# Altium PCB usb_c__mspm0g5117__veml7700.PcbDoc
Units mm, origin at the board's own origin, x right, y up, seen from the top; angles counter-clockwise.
Board outline 92 x 60 mm, 2 copper layers (Top, Bottom), stack 0 mm thick; 31 components, 27 nets, 168 pads, 52 vias.
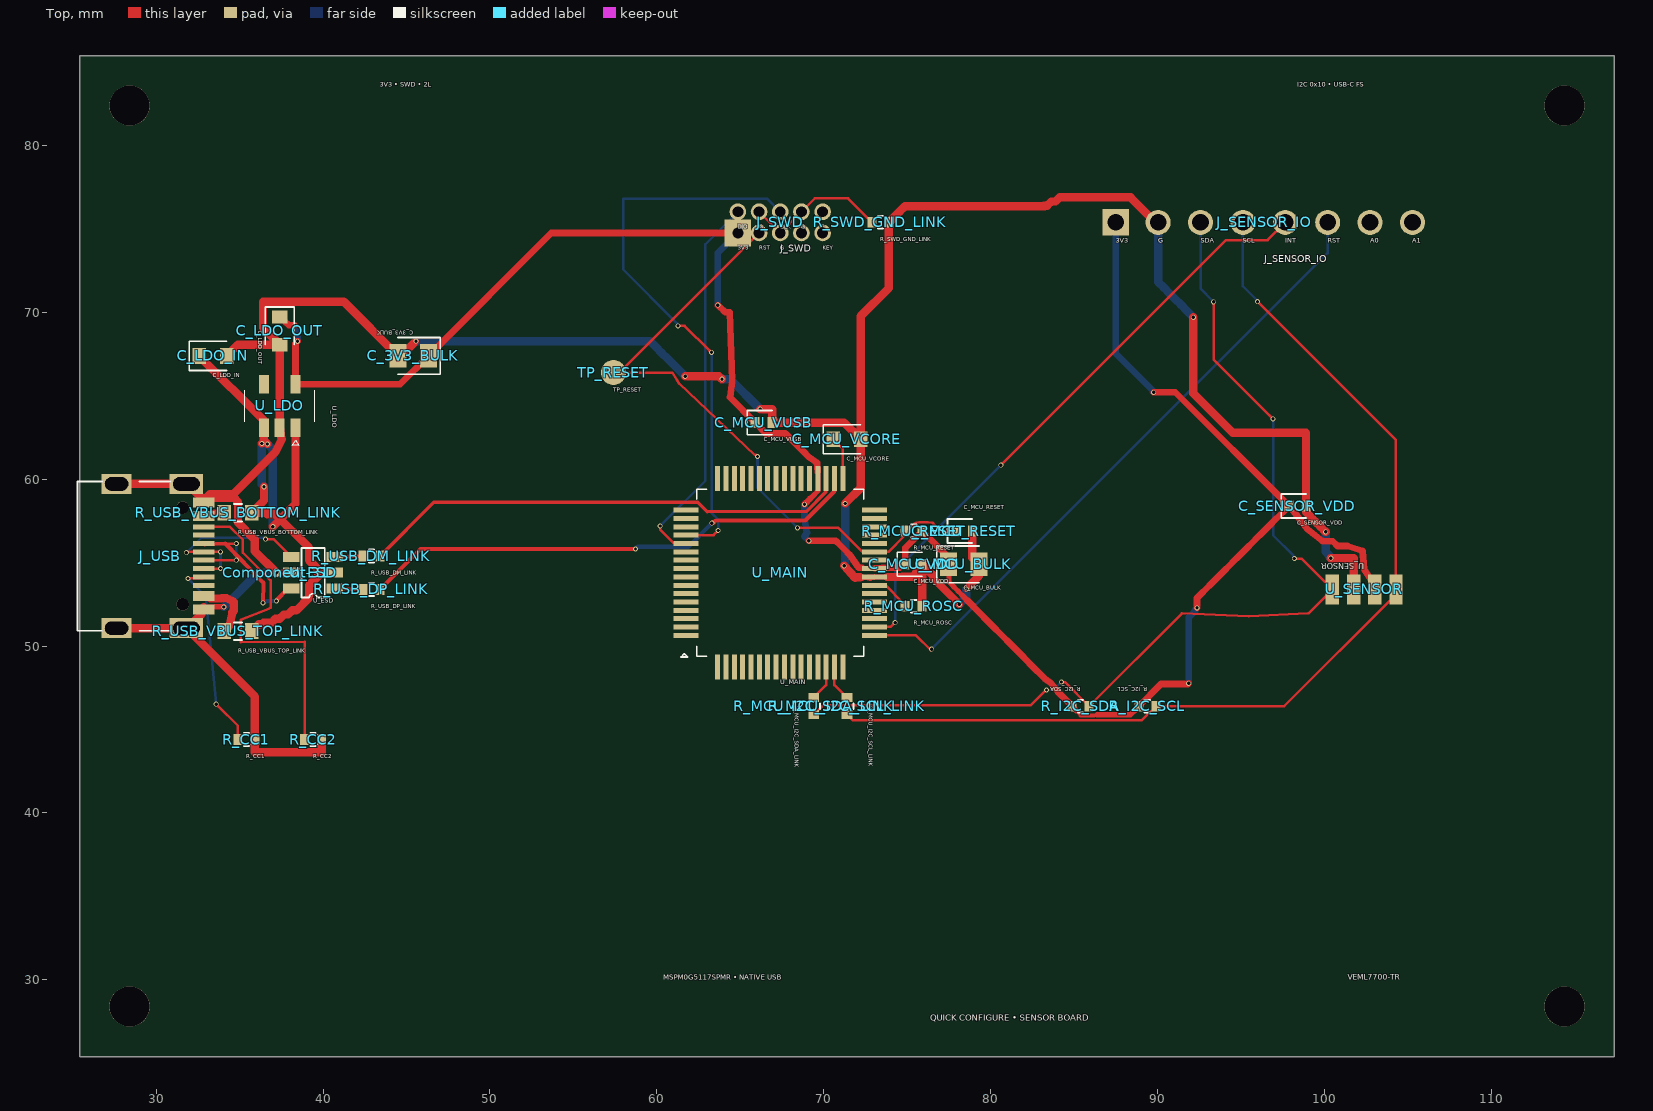
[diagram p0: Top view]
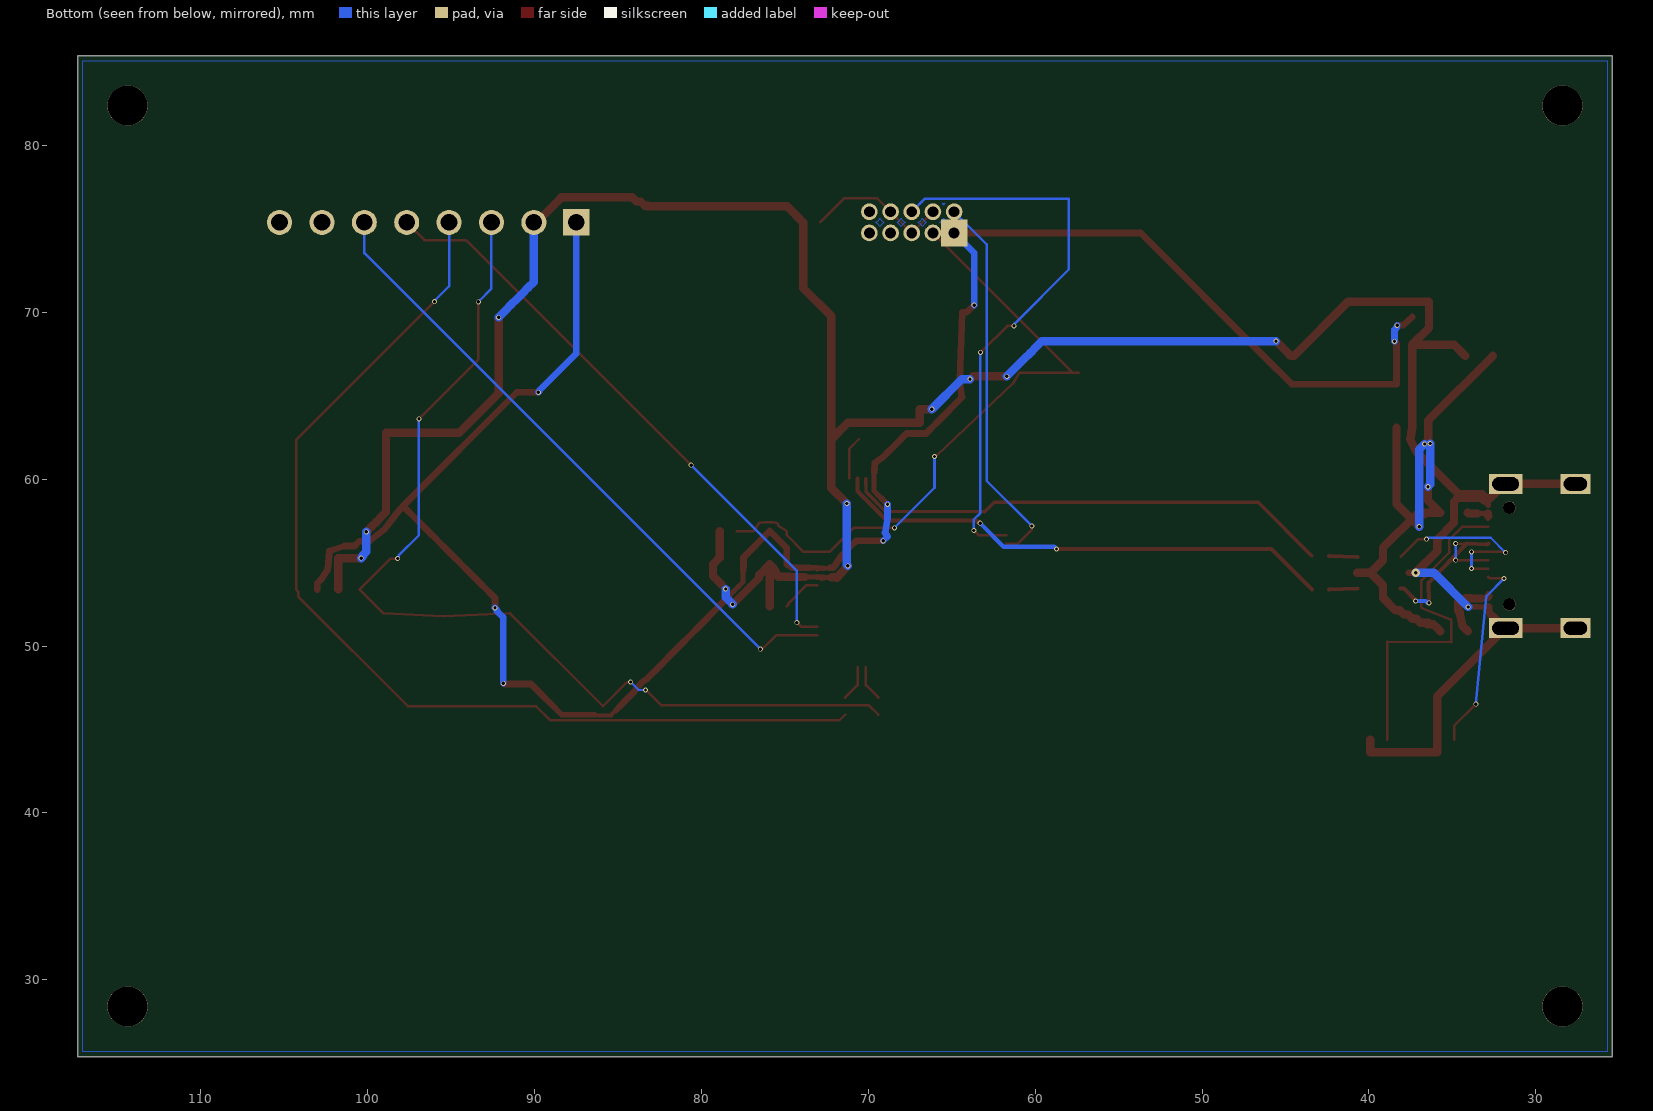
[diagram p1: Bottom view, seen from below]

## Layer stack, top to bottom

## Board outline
25.4,85.4 117.4,85.4 117.4,25.4 25.4,25.4

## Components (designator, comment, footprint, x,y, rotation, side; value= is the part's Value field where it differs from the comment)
C_3V3_BULK "" TSCIRCUIT-2.8500x1.4000mm 45.4,67.4 r180 top
C_LDO_IN "" TSCIRCUIT-2.4500x0.9500mm 33.4,67.4 r0 top
C_LDO_OUT "" TSCIRCUIT-0.9500x2.4500mm 37.4,68.9 r270 top
C_MCU_BULK "" TSCIRCUIT-2.8500x1.4000mm 78.4,54.9 r0 top
C_MCU_RESET "" TSCIRCUIT-1.5600x0.6400mm 78.4,56.9 r0 top
C_MCU_VCORE "" TSCIRCUIT-2.4500x0.9500mm 71.4,62.4 r0 top
C_MCU_VDD "" TSCIRCUIT-1.5600x0.6400mm 75.4,54.9 r0 top
C_MCU_VUSB "" TSCIRCUIT-1.5600x0.6400mm 66.4,63.4 r0 top
C_SENSOR_VDD "" TSCIRCUIT-1.5600x0.6400mm 98.4,58.4 r0 top
Component-31 "" TSCIRCUIT-0.5000x0.5000mm 37.2,54.4 r0 top
J_SENSOR_IO "" TSCIRCUIT-19.2800x1.5000mm 96.4,75.4 r0 top
J_SWD "" TSCIRCUIT-6.0800x2.2700mm 67.4,75.4 r0 top
J_USB "" TSCIRCUIT-6.7732x9.8502mm 30.113,55.4 r90 top
R_CC1 "" TSCIRCUIT-1.5600x0.6400mm 35.4,44.4 r0 top
R_CC2 "" TSCIRCUIT-1.5600x0.6400mm 39.4,44.4 r0 top
R_I2C_SCL "" TSCIRCUIT-1.5600x0.6400mm 89.4,46.4 r180 top
R_I2C_SDA "" TSCIRCUIT-1.5600x0.6400mm 85.4,46.4 r180 top
R_MCU_I2C_SCL_LINK "" TSCIRCUIT-0.6400x1.5600mm 71.4,46.4 r270 top
R_MCU_I2C_SDA_LINK "" TSCIRCUIT-0.6400x1.5600mm 69.4,46.4 r270 top
R_MCU_RESET "" TSCIRCUIT-1.5600x0.6400mm 75.4,56.9 r0 top
R_MCU_ROSC "" TSCIRCUIT-1.5600x0.6400mm 75.4,52.4 r0 top
R_SWD_GND_LINK "" TSCIRCUIT-1.5600x0.6400mm 73.4,75.4 r0 top
R_USB_DM_LINK "" TSCIRCUIT-1.5600x0.6400mm 42.9,55.4 r0 top
R_USB_DP_LINK "" TSCIRCUIT-1.5600x0.6400mm 42.9,53.4 r0 top
R_USB_VBUS_BOTTOM_LINK "" TSCIRCUIT-2.4500x0.9500mm 34.9,58 r0 top
R_USB_VBUS_TOP_LINK "" TSCIRCUIT-2.4500x0.9500mm 34.9,50.9 r0 top
TP_RESET "" TSCIRCUIT-1.5000x1.5000mm 57.4,66.4 r0 top
U_ESD "" TSCIRCUIT-3.6000x2.5000mm 39.4,54.4 r0 top
U_LDO "" TSCIRCUIT-2.5000x3.7000mm 37.4,64.4 r270 top
U_MAIN "" TSCIRCUIT-12.8000x12.8000mm 67.4,54.4 r0 top
U_SENSOR "" TSCIRCUIT-4.6100x1.8000mm 102.4,53.4 r0 top

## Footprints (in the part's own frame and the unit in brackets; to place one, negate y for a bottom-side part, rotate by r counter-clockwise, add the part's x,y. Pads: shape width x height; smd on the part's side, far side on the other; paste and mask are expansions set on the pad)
TSCIRCUIT-0.5000x0.5000mm [mm]
TSCIRCUIT-0.6400x1.5600mm [mm]
  rect 0.54x0.64 smd: 1(-0.51,0) 2(0.51,0)
  silkscreen extent -0.15,-0.38 0.15,0.38
TSCIRCUIT-0.9500x2.4500mm [mm]
  rect 0.8x0.95 smd: 1(-0.825,0) 2(0.825,0)
  silkscreen extent -1.43,-0.87 0.82,0.88
TSCIRCUIT-1.5000x1.5000mm [mm]
  round 1.5 smd: 1(0,0)
TSCIRCUIT-1.5600x0.6400mm [mm]
  rect 0.54x0.64 smd: 1(-0.51,0) 2(0.51,0)
  silkscreen extent -0.98,-0.72 0.51,0.72
TSCIRCUIT-2.4500x0.9500mm [mm]
  rect 0.8x0.95 smd: 1(-0.825,0) 2(0.825,0)
  silkscreen extent -1.42,-0.87 0.82,0.87
TSCIRCUIT-2.5000x3.7000mm [mm]
  rect 1.1x0.6 smd: 1(1.3,0.95) 2(1.3,0) 3(1.3,-0.95) 4(-1.3,-0.95) 5(-1.3,0.95)
  silkscreen extent -0.95,-2.1 2.35,2.1
TSCIRCUIT-2.8500x1.4000mm [mm]
  rect 1.025x1.4 smd: 1(-0.913,0) 2(0.913,0)
  silkscreen extent -1.63,-1.1 0.91,1.1
TSCIRCUIT-3.6000x2.5000mm [mm]
  rect 1x0.6 smd: 1(-1.3,-0.95) 2(-1.3,0) 3(-1.3,0.95) 4(1.3,0.95) 5(1.3,0) 6(1.3,-0.95)
  silkscreen extent -0.7,-1.49 0.7,1.49
TSCIRCUIT-4.6100x1.8000mm [mm]
  rect 0.8x1.8 smd: 1(1.905,0) 2(0.635,0) 3(-0.635,0) 4(-1.905,0)
TSCIRCUIT-6.0800x2.2700mm [mm]
  rect 1.6x1.6 hole 0.65: 1(-2.54,-0.635)
  round 1 hole 0.65: 2(-2.54,0.635) 3(-1.27,0.635) 4(0,0.635) 5(1.27,0.635) 6(2.54,0.635) 7(2.54,-0.635) 8(1.27,-0.635) 9(0,-0.635) 10(-1.27,-0.635)
TSCIRCUIT-6.7732x9.8502mm [mm]
  rect 0.3x1.3 smd: 1(-3.35,-2.737) 2(-3.05,-2.737) 3(-2.55,-2.737) 4(-2.25,-2.737) 5(-1.75,-2.737) 6(-1.25,-2.737) 7(-0.75,-2.737) 8(-0.25,-2.737) 9(0.25,-2.737) 10(0.75,-2.737) 11(1.25,-2.737) 12(1.75,-2.737) 13(2.55,-2.737) 14(2.25,-2.737) 15(3.35,-2.737) 16(3.05,-2.737)
  rect 1.2x2 hole 0.8 slot 1.6 at 90 deg: 17(-4.325,-1.693) 18(4.325,-1.693)
  rect 1.2x1.8 hole 0.8 slot 1.4 at 90 deg: 19(4.325,2.487) 20(-4.325,2.487)
  round 0.75 hole 0.75 unplated: NPTH-1(-2.9,-1.468) NPTH-2(2.9,-1.468)
  silkscreen extent -4.47,-0.75 4.47,4.83
TSCIRCUIT-12.8000x12.8000mm [mm]
  rect 1.5x0.3 smd: 1(-5.65,-3.75) 2(-5.65,-3.25) 3(-5.65,-2.75) 4(-5.65,-2.25) 5(-5.65,-1.75) 6(-5.65,-1.25) 7(-5.65,-0.75) 8(-5.65,-0.25) 9(-5.65,0.25) 10(-5.65,0.75) 11(-5.65,1.25) 12(-5.65,1.75) 13(-5.65,2.25) 14(-5.65,2.75) 15(-5.65,3.25) 16(-5.65,3.75) 33(5.65,3.75) 34(5.65,3.25) 35(5.65,2.75) 36(5.65,2.25) 37(5.65,1.75) 38(5.65,1.25) 39(5.65,0.75) 40(5.65,0.25) 41(5.65,-0.25) 42(5.65,-0.75) 43(5.65,-1.25) 44(5.65,-1.75) 45(5.65,-2.25) 46(5.65,-2.75) 47(5.65,-3.25) 48(5.65,-3.75)
  rect 0.3x1.5 smd: 17(-3.75,5.65) 18(-3.25,5.65) 19(-2.75,5.65) 20(-2.25,5.65) 21(-1.75,5.65) 22(-1.25,5.65) 23(-0.75,5.65) 24(-0.25,5.65) 25(0.25,5.65) 26(0.75,5.65) 27(1.25,5.65) 28(1.75,5.65) 29(2.25,5.65) 30(2.75,5.65) 31(3.25,5.65) 32(3.75,5.65) 49(3.75,-5.65) 50(3.25,-5.65) 51(2.75,-5.65) 52(2.25,-5.65) 53(1.75,-5.65) 54(1.25,-5.65) 55(0.75,-5.65) 56(0.25,-5.65) 57(-0.25,-5.65) 58(-0.75,-5.65) 59(-1.25,-5.65) 60(-1.75,-5.65) 61(-2.25,-5.65) 62(-2.75,-5.65) 63(-3.25,-5.65) 64(-3.75,-5.65)
  silkscreen extent -5.95,-5.05 5,5
TSCIRCUIT-19.2800x1.5000mm [mm]
  rect 1.6x1.6 hole 1: 1(-8.89,0)
  round 1.5 hole 1: 2(-6.35,0) 3(-3.81,0) 4(-1.27,0) 5(1.27,0) 6(3.81,0) 7(6.35,0) 8(8.89,0)

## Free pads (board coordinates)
  round 2.4 hole 2.4 unplated: NPTH-3(28.4,28.4) NPTH-4(114.4,28.4) NPTH-5(28.4,82.4) NPTH-6(114.4,82.4)

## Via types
v1: diameter 0.3, hole 0.2, Top to Bottom, 51 vias
v2: diameter 0.5, hole 0.2, Top to Bottom, 1 vias

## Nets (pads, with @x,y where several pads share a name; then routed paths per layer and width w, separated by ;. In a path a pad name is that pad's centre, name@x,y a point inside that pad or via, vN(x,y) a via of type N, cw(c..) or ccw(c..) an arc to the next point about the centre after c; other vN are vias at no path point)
".J_SWD > .pin2 to .U_MAIN > .pin12": J_SWD.2 U_MAIN.12 | length 22.9
  Top w0.15: v1(60.2,57.2) 60.2,56.987 61.037,56.15 U_MAIN.12
  Bottom w0.15: v1(60.2,57.2) 62.903,59.903 62.903,74.078 J_SWD.2
".J_SWD > .pin4 to .U_MAIN > .pin13": J_SWD.4 U_MAIN.13 | length 34.3
  Top w0.15: v1(61.273,69.197) 61.668,69.197 63.155,67.709 63.177,67.709 v1(63.28,67.606) ; U_MAIN.13 63.4,56.65 v1(63.683,56.933)
  Bottom w0.15: v1(61.273,69.197) 61.219,69.251 61.219,69.348 57.975,72.592 57.975,76.819 66.616,76.819 J_SWD.4 ; v1(63.28,67.606) 63.28,57.987 63.691,57.576 63.691,57.077 63.691,56.941 v1(63.683,56.933)
".U_MAIN > .pin42 to .R_MCU_ROSC > .pin1": R_MCU_ROSC.1 U_MAIN.42 | length 2.4
  Top w0.15: U_MAIN.42 73.713,53.658 74.762,52.598 74.76,52.53 R_MCU_ROSC.1
GND: C_3V3_BULK.2 C_LDO_IN.2 C_LDO_OUT.2 C_MCU_BULK.2 C_MCU_RESET.2 C_MCU_VCORE.2 C_MCU_VDD.2 C_MCU_VUSB.2 C_SENSOR_VDD.2 J_SENSOR_IO.2 J_USB.1 J_USB.2 J_USB.15 J_USB.16 J_USB.17 J_USB.18 J_USB.19 J_USB.20 R_CC1.2 R_CC2.2 R_MCU_ROSC.2 R_SWD_GND_LINK.2 U_ESD.2 U_LDO.2 U_MAIN.41 U_SENSOR.3 | length 183.4
  Top w0.275: J_USB.2 J_USB.2@33.25,52.35
  Top w0.3: J_USB.1@32.699,51.9 J_USB.1 J_USB.1@32.849,52.2 ; J_USB.15@32.699,58.9 J_USB.15 ; J_USB.16 32.999,58.6 33.04,58.641 33.141,58.641 33.4,58.9 33.499,58.9 ; J_USB.16@32.849,58.6 J_USB.15 ; J_USB.15@32.999,58.9 J_USB.15 ; J_USB.2@33.25,52.35 33.499,52.35 ; 72.3,54.12 72.425,54.12 72.55,54.12 U_MAIN.41@72.675,54.117 ; U_MAIN.41 73.144,54.15 73.237,54.15 73.331,54.15 73.425,54.15 73.519,54.15 73.612,54.15 73.706,54.15 U_MAIN.41@73.8,54.15
  Top w0.325: J_USB.16 J_USB.16@32.849,58.6 ; 33.499,52.35 33.651,52.35 v1(34.053,52.35)
  Top w0.337: U_MAIN.41@72.675,54.117 U_MAIN.41@72.796,54.106
  Top w0.35: v1(78.551,53.425) v1@78.567,53.441
  Top w0.375: 45.429,68.145 45.435,68.145 v1(45.568,68.278) ; U_MAIN.41@72.796,54.106 U_MAIN.41
  Top w0.4: 37.2,54.4 U_ESD.2@37.6,54.4 ; 72.175,54.12 72.3,54.12 ; v1@78.567,53.441 v1@78.567,53.459
  Top w0.425: v1@78.567,53.459 78.815,53.708
  Top w0.437: 76.536,54.102 v1(78.132,52.506)
  Top w0.45: 76.536,54.102 76.536,54.256
  Top w0.475: U_MAIN.41@73.8,54.15 74.253,54.15 74.707,54.15
  Top w0.5: J_USB.20 J_USB.17 ; J_USB.19 J_USB.18 31.874,59.725 32.474,59.125 32.699,58.9 ; 32.699,51.9 32.474,51.675 31.874,51.075 J_USB.17 ; J_USB.1@32.849,52.2 J_USB.2 ; 32.999,58.9 33.199,59.1 34.6,59.1 37.15,61.65 37.512,62.398 37.456,62.749 U_LDO.2 C_LDO_OUT.2 ; 33.499,58.9 34.65,58.9 34.9,58.65 34.9,57.4 35.9,56.4 35.9,55.7 37.2,54.4 ; C_LDO_IN.2 34.9,68.075 C_LDO_OUT.2 ; R_CC2.2 39.91,43.65 35.91,43.65 R_CC1.2 35.91,46.971 J_USB.17 ; 45.429,68.145 45.181,67.897 44.932,67.648 44.684,67.4 C_3V3_BULK.2 41.237,70.65 36.4,70.65 36.4,69.075 C_LDO_OUT.2 ; v1(61.702,66.175) 62.107,66.175 62.513,66.175 62.918,66.175 63.324,66.175 63.729,66.175 63.885,66.019 63.908,66.019 v1(63.912,66) ; v1(66.2,64.2) 66.91,64.2 C_MCU_VUSB.2 71.225,63.4 C_MCU_VCORE.2 ; v1(71.23,54.813) 71.902,54.081 72.05,54.12 72.175,54.12 ; v1(71.292,58.547) 72.225,59.48 C_MCU_VCORE.2 ; 74.707,54.15 75.4,54.15 75.66,54.65 C_MCU_VDD.2 ; R_MCU_ROSC.2 C_MCU_VDD.2 ; 76.536,54.256 76.536,54.274 C_MCU_VDD.2 ; 78.815,53.708 79.064,53.956 79.313,54.205 79.313,54.552 C_MCU_BULK.2 78.91,55.303 C_MCU_RESET.2 ; J_SENSOR_IO.2 89.9,75.4 88.4,76.9 84.15,76.9 83.9,76.65 83.65,76.65 83.4,76.4 83.202,76.4 83.235,76.366 82.748,76.366 82.261,76.366 81.773,76.366 81.286,76.366 80.799,76.366 80.311,76.366 79.824,76.366 79.337,76.366 78.849,76.366 78.362,76.366 77.875,76.366 77.387,76.366 76.9,76.366 76.413,76.366 75.925,76.366 75.438,76.366 74.951,76.366 74.876,76.366 74.554,76.044 74.232,75.722 R_SWD_GND_LINK.2 73.91,71.464 72.225,69.779 72.225,69.287 72.225,68.795 72.225,68.303 72.225,67.812 72.225,67.32 72.225,66.828 72.225,66.336 72.225,65.844 72.225,65.352 72.225,64.86 72.225,64.368 72.225,63.876 72.225,63.384 72.225,62.892 C_MCU_VCORE.2 ; v1(92.163,69.711) 92.163,69.255 92.163,68.798 92.163,68.342 92.163,67.885 92.163,67.429 92.163,66.973 92.163,66.516 92.163,66.06 92.163,65.603 92.163,65.147 92.5,64.81 92.838,64.472 93.175,64.135 93.512,63.798 93.85,63.46 94.187,63.123 94.524,62.786 98.91,62.786 C_SENSOR_VDD.2 98.91,58.03 99.198,57.742 99.486,57.454 99.774,57.166 100.062,56.878 v1(100.086,56.854) ; v1(100.398,55.276) 101.765,55.276 U_SENSOR.3
  Bottom w0.5: v1(34.053,52.35) 36.103,54.4 37.2,54.4 ; v1(45.568,68.278) 46.052,68.278 46.536,68.278 47.019,68.278 47.503,68.278 47.987,68.278 48.471,68.278 48.955,68.278 49.439,68.278 49.922,68.278 50.406,68.278 50.89,68.278 51.374,68.278 51.858,68.278 52.342,68.278 52.825,68.278 53.309,68.278 53.793,68.278 54.277,68.278 54.761,68.278 55.245,68.278 55.728,68.278 56.212,68.278 56.696,68.278 57.18,68.278 57.664,68.278 58.148,68.278 58.631,68.278 59.115,68.278 59.599,68.278 59.947,67.93 60.295,67.582 60.642,67.235 60.99,66.887 61.338,66.539 61.686,66.191 v1(61.702,66.175) ; v1(63.912,66) 64.4,66 v1(66.2,64.2) ; v1(71.23,54.813) 71.292,54.875 v1(71.292,58.547) ; v1(78.132,52.506) 78.193,52.567 78.193,52.574 78.372,52.753 78.551,52.933 v1(78.551,53.425) ; J_SENSOR_IO.2 90.05,74.953 90.05,74.506 90.05,74.059 90.05,73.612 90.05,73.165 90.05,72.718 90.05,72.271 90.05,71.824 90.389,71.485 90.728,71.146 91.067,70.807 91.406,70.468 91.745,70.129 92.084,69.79 v1(92.163,69.711) ; v1(100.086,56.854) 100.086,56.457 100.086,56.061 100.086,55.664 100.305,55.446 100.305,55.369 v1(100.398,55.276)
MAIN_RESET: C_MCU_RESET.1 J_SWD.10 R_MCU_RESET.1 TP_RESET.1 U_MAIN.38 | length 39.4
  Top w0.15: v1(66.036,61.371) 65.94,61.467 65.87,61.467 61.348,65.731 60.937,66.4 TP_RESET.1 57.765,66.4 J_SWD.10 ; v1(68.435,57.088) 70.889,57.088 72.31,55.667 73.033,55.667 U_MAIN.38 73.889,55.65 74.889,56.651 R_MCU_RESET.1@74.889,56.899 ; R_MCU_RESET.1 75.4,57.22 75.434,57.351 75.542,57.405 75.741,57.423 76.047,57.425 76.251,57.425 76.537,57.386 76.892,56.9 C_MCU_RESET.1
  Bottom w0.15: v1(66.036,61.371) 66.036,59.492 68.418,57.11 68.418,57.105 v1(68.435,57.088)
MCU_I2C_SCL_LOCAL: R_MCU_I2C_SCL_LINK.1 U_MAIN.50 | length 2.2
  Top w0.15: U_MAIN.50 70.65,47.66 R_MCU_I2C_SCL_LINK.1
MCU_I2C_SDA_LOCAL: R_MCU_I2C_SDA_LINK.1 U_MAIN.51 | length 2.2
  Top w0.15: R_MCU_I2C_SDA_LINK.1 70.15,47.66 U_MAIN.51
MSPM0_VCORE: C_MCU_VCORE.1 U_MAIN.32 | length 2.6
  Top w0.15: C_MCU_VCORE.1 71.15,61.825 U_MAIN.32
SENSOR_ADDR0: J_SENSOR_IO.7
SENSOR_ADDR1: J_SENSOR_IO.8
SENSOR_INT: J_SENSOR_IO.5 U_MAIN.47 | length 36.5
  Top w0.15: U_MAIN.47 74,51.15 74.212,51.362 74.238,51.362 v1(74.287,51.411) ; v1(80.625,60.847) 94.118,74.34 96.61,74.34 J_SENSOR_IO.5
  Bottom w0.15: v1(74.287,51.411) 74.287,54.509 80.58,60.802 v1(80.625,60.847)
SENSOR_RESET: J_SENSOR_IO.6 U_MAIN.48 | length 39.2
  Top w0.15: U_MAIN.48 75.532,50.65 76.428,49.753 76.428,49.776 v1(76.472,49.82)
  Bottom w0.15: v1(76.472,49.82) 100.21,73.558 J_SENSOR_IO.6
SENSOR_SCL: J_SENSOR_IO.4 R_I2C_SCL.1 R_MCU_I2C_SCL_LINK.2 U_SENSOR.1 | length 62.3
  Top w0.15: R_MCU_I2C_SCL_LINK.2 71.743,45.547 89.014,45.547 89.057,45.547 R_I2C_SCL.1 97.597,46.4 104.162,52.957 104.158,53.253 U_SENSOR.1 104.305,62.354 v1(96.008,70.651)
  Bottom w0.15: J_SENSOR_IO.4 95.13,71.573 95.959,70.744 95.959,70.7 v1(96.008,70.651)
SENSOR_SDA: J_SENSOR_IO.3 R_I2C_SDA.1 R_MCU_I2C_SDA_LINK.2 U_SENSOR.4 | length 60.9
  Top w0.15: R_MCU_I2C_SDA_LINK.2 69.971,46.448 82.163,46.459 82.42,46.461 83.299,47.34 83.331,47.34 v1(83.362,47.371) ; v1(84.249,47.851) 84.459,47.851 R_I2C_SDA.1 91.47,51.958 95.475,51.8 99.055,51.96 U_SENSOR.4 98.646,55.249 v1(98.213,55.249) ; v1(93.377,70.642) 93.377,67.185 96.765,63.797 v1(96.937,63.625)
  Bottom w0.15: v1(83.362,47.371) 83.786,47.388 84.204,47.806 v1(84.249,47.851) ; J_SENSOR_IO.3 92.59,71.429 93.317,70.702 v1(93.377,70.642) ; v1(96.937,63.625) 96.937,56.647 98.161,55.423 98.161,55.301 v1(98.213,55.249)
swd-ground-1-to-2: J_SWD.3 J_SWD.5 J_SWD.9 R_SWD_GND_LINK.1 | length 8.8
  Top w0.15: J_SWD.3 J_SWD.9 J_SWD.5 69.481,76.846 71.471,76.846 71.471,76.819 R_SWD_GND_LINK.1
usb-dm-device: R_USB_DM_LINK.1 U_ESD.4 | length 1.7
  Top w0.25: U_ESD.4 R_USB_DM_LINK.1
usb-dm-mcu: R_USB_DM_LINK.2 U_MAIN.30 | length 29.6
  Top w0.2: R_USB_DM_LINK.2 46.638,58.628 62.455,58.628 63.023,58.061 68.962,58.069 70.142,59.249 U_MAIN.30
usb-dm-port-tie: J_USB.7 J_USB.9 U_ESD.3 | length 11.2
  Top w0.15: v1(31.8,55.6) 31.87,55.6 31.92,55.65 J_USB.9 v1(33.85,55.65) ; J_USB.7 v1(33.85,54.65) ; v1(36.552,56.413) 37.037,56.413 U_ESD.3
  Bottom w0.15: v1(31.8,55.6) 32.697,56.497 36.165,56.497 36.457,56.497 36.546,56.407 v1(36.552,56.413) ; v1(33.85,54.65) v1(33.85,55.65)
usb-dp-device: R_USB_DP_LINK.1 U_ESD.6 | length 1.7
  Top w0.25: U_ESD.6 R_USB_DP_LINK.1
usb-dp-mcu: R_USB_DP_LINK.2 U_MAIN.31 | length 30.5
  Top w0.25: R_USB_DP_LINK.2 45.837,55.827 v1(58.728,55.827) ; v1(63.302,57.373) 63.358,57.429 63.43,57.429 63.531,57.53 68.895,57.522 70.658,59.285 U_MAIN.31
  Bottom w0.25: v1(58.728,55.827) 58.861,55.96 58.89,55.96 61.889,55.96 v1(63.302,57.373)
usb-dp-port-tie: J_USB.8 J_USB.10 U_ESD.1 | length 12.8
  Top w0.15: J_USB.8 v1(34.8,55.15) ; J_USB.10 v1(34.8,56.15)
  Top w0.25: J_USB.10 32.909,56.09 34.135,56.153 36.435,53.797 v1(36.4,52.6) ; v1@37.201,52.711 37.201,52.75 37.901,53.45 U_ESD.1
  Bottom w0.15: v1(34.8,55.15) v1(34.8,56.15)
  Bottom w0.25: v1(36.4,52.6) 36.404,52.604 36.496,52.604 36.603,52.711 v1(37.201,52.711)
USB_CC1: J_USB.6 R_CC1.1 | length 11.7
  Top w0.15: v1(31.901,54.055) 32.754,54.055 J_USB.6 ; v1(33.586,46.524) 33.699,46.411 33.709,46.411 34.89,45.23 R_CC1.1
  Bottom w0.15: v1(31.901,54.055) 31.894,54.048 32.952,52.991 v1(33.586,46.524)
USB_CC2: J_USB.12 R_CC2.1 | length 20.4
  Top w0.15: J_USB.12 34.418,57.15 35.182,56.386 35.182,55.613 36.855,53.94 36.855,52.307 36.75,52.25 35.063,51.575 35.063,50.225 38.89,50.271 R_CC2.1
USB_VBUS_BOTTOM_LOCAL: J_USB.13 J_USB.14 R_USB_VBUS_BOTTOM_LINK.1 | length 1.5
  Top w0.3: J_USB.14 J_USB.14@32.849,57.8 ; J_USB.13 32.927,57.95 33.005,57.95 33.083,57.95 33.161,57.95 33.239,57.95 33.317,57.95 33.394,57.95 33.472,57.95 33.499,57.95
  Top w0.475: J_USB.13@32.849,57.8 J_USB.13 ; 33.499,57.95 R_USB_VBUS_BOTTOM_LINK.1@33.762,57.95
  Top w0.5: R_USB_VBUS_BOTTOM_LINK.1@33.762,57.95 34.025,57.95 R_USB_VBUS_BOTTOM_LINK.1
USB_VBUS_TOP_LOCAL: J_USB.3 J_USB.4 R_USB_VBUS_TOP_LINK.1 | length 4.1
  Top w0.275: J_USB.3 J_USB.3@33.247,52.85
  Top w0.3: J_USB.3 32.849,53 J_USB.4
  Top w0.475: J_USB.3@33.247,52.85 33.644,52.85 33.928,52.867
  Top w0.5: 33.928,52.867 33.945,52.884 34.212,52.884 34.65,52.65 34.65,52.123 34.562,52.035 34.475,51.623 34.387,51.211 R_USB_VBUS_TOP_LINK.1
VBUS5: C_LDO_IN.1 R_USB_VBUS_BOTTOM_LINK.2 R_USB_VBUS_TOP_LINK.2 U_ESD.5 U_LDO.1 U_LDO.3 | length 38.2
  Top w0.5: C_LDO_IN.1 36.45,63.525 U_LDO.3 ; R_USB_VBUS_TOP_LINK.2 35.93,51.106 36.136,51.311 36.521,51.311 36.431,51.4 36.9,51.4 37.15,51.65 37.4,51.65 37.65,51.9 37.9,51.9 38.15,52.15 38.4,52.15 39.15,52.9 39.15,53.65 39.9,54.4 ; v1(36.325,62.15) 36.45,62.275 U_LDO.3 ; v1(36.459,59.554) 36.459,59.144 36.459,58.734 36.214,58.489 35.97,58.245 R_USB_VBUS_BOTTOM_LINK.2 36.225,58 36.725,58 36.65,57.925 36.65,57.9 37.15,57.9 39.15,55.9 39.15,55.15 39.9,54.4 ; v1(36.656,62.118) 36.45,62.325 U_LDO.3 ; v1(36.985,57.166) 38.35,58.531 U_LDO.1 ; 39.9,54.4 U_ESD.5 39.9,54.4
  Bottom w0.5: v1(36.325,62.15) 36.325,59.688 v1(36.459,59.554) ; v1(36.656,62.118) 36.985,61.79 v1(36.985,57.166)
VCC_3V3: C_3V3_BULK.1 C_LDO_OUT.1 C_MCU_BULK.1 C_MCU_VDD.1 C_MCU_VUSB.1 C_SENSOR_VDD.1 J_SENSOR_IO.1 J_SWD.1 R_I2C_SCL.2 R_I2C_SDA.2 R_MCU_RESET.2 U_LDO.5 U_MAIN.29 U_MAIN.40 U_SENSOR.2 | length 133.6
  Top w0.25: R_I2C_SDA.2@85.143,46.147 85.396,45.894 85.4,45.85 85.667,45.85 85.933,45.85 86.2,45.85 86.395,45.89
  Top w0.3: 69.437,59.075 69.65,59.3 69.65,59.675 U_MAIN.29 U_MAIN.29@69.65,60.425 ; 72.3,54.689 U_MAIN.40 ; C_MCU_BULK.1@77.499,54.546 77.511,54.191 77.523,53.837 77.796,53.562
  Top w0.306: U_MAIN.40@73.48,54.699 73.162,54.706 U_MAIN.40@73.509,54.704
  Top w0.312: 77.796,53.562 78.069,53.286 78.342,53.011
  Top w0.325: 69.184,58.834 69.225,58.85 69.437,59.075 ; 86.395,45.89 86.793,45.891
  Top w0.33: U_MAIN.40 72.718,54.684 73.099,54.692 U_MAIN.40@73.48,54.699
  Top w0.337: R_I2C_SDA.2 R_I2C_SDA.2@85.143,46.147 ; 86.793,45.891 87.191,45.891 87.588,45.892 87.986,45.892 88.384,45.893 88.637,46.147 R_I2C_SCL.2
  Top w0.35: 78.342,53.011 78.615,52.735
  Top w0.363: v1(68.85,58.5) 68.952,58.602 69.184,58.834
  Top w0.387: U_MAIN.40@73.509,54.704 73.856,54.703
  Top w0.4: C_LDO_OUT.1 37.96,69.228 v1(38.304,69.229) ; v1(38.469,68.274) 38.399,68.269 38.399,68.18 38.35,68.131 U_LDO.5 44.613,65.7 C_3V3_BULK.1 53.678,74.765 J_SWD.1 ; v1(63.655,70.439) 63.781,70.313 63.803,70.313 64.095,70.021 64.378,70.021 64.515,65.907 64.392,64.918 C_MCU_VUSB.1 66.109,63.181 66.327,62.963 66.546,62.744 66.932,62.744 67.319,62.744 67.706,62.744 67.983,62.467 68.261,62.189 68.539,61.911 68.817,61.633 69.094,61.356 69.6,61 U_MAIN.29@69.65,60.425 ; v1(69.114,56.313) 69.438,56.313 69.762,56.313 70.086,56.312 70.41,56.312 70.734,56.312 70.999,56.045 71.264,55.777 71.528,55.51 72.1,54.7 72.3,54.689 ; 73.856,54.703 74.203,54.701 74.55,54.7 C_MCU_VDD.1 74.89,55.88 R_MCU_RESET.2 77.488,55.323 C_MCU_BULK.1 C_MCU_BULK.1@77.499,54.546 ; 78.615,52.735 78.887,52.46 79.16,52.184 79.433,51.909 79.706,51.633 79.979,51.358 80.252,51.083 80.525,50.807 80.797,50.532 81.07,50.256 81.343,49.981 81.616,49.705 81.889,49.43 82.162,49.154 82.434,48.879 82.707,48.604 82.98,48.328 83.253,48.053 83.6,47.8 84.071,47.226 84.344,46.951 84.617,46.675 R_I2C_SDA.2 ; R_I2C_SCL.2 89.156,46.666 89.423,46.933 89.689,47.199 89.956,47.466 90.222,47.732 90.545,47.732 90.868,47.732 91.192,47.732 91.515,47.732 91.838,47.732 v1(91.876,47.77) ; v1(89.779,65.217) 91.073,65.217 C_SENSOR_VDD.1 ; v1(92.38,52.298) 92.38,52.594 92.38,52.89 92.655,53.165 92.931,53.441 93.206,53.716 93.482,53.992 93.758,54.267 94.033,54.543 94.309,54.819 94.584,55.094 94.86,55.37 95.135,55.645 95.411,55.921 95.686,56.196 95.961,56.471 96.237,56.747 96.512,57.022 96.788,57.298 97.063,57.573 97.339,57.849 97.615,58.124 C_SENSOR_VDD.1 ; U_SENSOR.2 103.035,53.768 102.755,54.048 102.4,54.6 102.3,55.7 101.4,56 100.795,56.008 100.515,56.288 100.258,56.288 99.9,56.3 99,57 98.238,57.99 98.064,58.195 C_SENSOR_VDD.1
  Bottom w0.4: v1(38.304,69.229) 38.348,69.119 38.348,69.077 38.469,68.956 v1(38.469,68.274) ; v1(63.655,70.439) 63.655,73.56 J_SWD.1 ; v1(68.85,58.5) 68.85,58.115 68.85,57.731 69,56.8 68.85,56.577 69.079,56.348 v1(69.114,56.313) ; J_SENSOR_IO.1 87.51,67.541 89.729,65.322 89.729,65.267 v1(89.779,65.217) ; v1(91.876,47.77) 91.876,48.165 91.876,48.56 91.876,48.954 91.876,49.349 91.876,49.744 91.876,50.139 91.876,50.534 91.876,50.928 91.876,51.323 91.876,51.718 92.071,51.913 92.266,52.108 92.266,52.181 v1(92.38,52.298)
pads on no net: J_SWD.6 J_SWD.7 J_SWD.8 J_USB.5 J_USB.11 J_USB.NPTH-1 J_USB.NPTH-2 U_LDO.4 U_MAIN.1 U_MAIN.2 U_MAIN.3 U_MAIN.4 U_MAIN.5 U_MAIN.6 U_MAIN.7 U_MAIN.8 U_MAIN.9 U_MAIN.10 U_MAIN.11 U_MAIN.14 U_MAIN.15 U_MAIN.16 U_MAIN.17 U_MAIN.18 U_MAIN.19 U_MAIN.20 U_MAIN.21 U_MAIN.22 U_MAIN.23 U_MAIN.24 U_MAIN.25 U_MAIN.26 U_MAIN.27 U_MAIN.28 U_MAIN.33 U_MAIN.34 U_MAIN.35 U_MAIN.36 U_MAIN.37 U_MAIN.39 U_MAIN.43 U_MAIN.44 U_MAIN.45 U_MAIN.46 U_MAIN.49 U_MAIN.52 U_MAIN.53 U_MAIN.54 U_MAIN.55 U_MAIN.56 U_MAIN.57 U_MAIN.58 U_MAIN.59 U_MAIN.60 U_MAIN.61 U_MAIN.62 U_MAIN.63 U_MAIN.64
copper on no net:
  other v2: 37.2,54.4

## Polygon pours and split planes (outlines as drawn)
GND on Bottom (solid): 117.1,85.1 25.7,85.1 25.7,25.7 117.1,25.7
GND on Bottom (solid): 65.582,76.544 65.408,76.544 65.484,76.452 65.495,76.43 65.506,76.452
GND on Bottom (solid): 65.495,75.64 65.484,75.618 65.399,75.515 65.591,75.515 65.506,75.618
GND on Bottom (solid): 65.61,75.496 65.61,75.304 65.713,75.389 65.735,75.4 65.713,75.411
GND on Bottom (solid): 69.305,75.64 69.294,75.618 69.2,75.505 69.087,75.411 69.065,75.4 69.087,75.389 69.2,75.295 69.294,75.182 69.305,75.16 69.316,75.182 69.41,75.295 69.523,75.389 69.545,75.4 69.523,75.411 69.41,75.505 69.316,75.618
GND on Bottom (solid): 68.035,75.64 68.024,75.618 67.93,75.505 67.817,75.411 67.795,75.4 67.817,75.389 67.93,75.295 68.024,75.182 68.035,75.16 68.046,75.182 68.14,75.295 68.253,75.389 68.275,75.4 68.253,75.411 68.14,75.505 68.046,75.618
GND on Bottom (solid): 66.765,75.64 66.754,75.618 66.66,75.505 66.547,75.411 66.525,75.4 66.547,75.389 66.66,75.295 66.754,75.182 66.765,75.16 66.776,75.182 66.87,75.295 66.983,75.389 67.005,75.4 66.983,75.411 66.87,75.505 66.776,75.618

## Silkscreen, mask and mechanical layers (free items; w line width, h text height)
Top Overlay:
  text "3V3 • SWD • 2L" at 43.4,83.4 h0.48
  text "I2C 0x10 • USB-C FS" at 98.4,83.4 h0.5
  text "MSPM0G5117SPMR • NATIVE USB" at 60.4,29.9 h0.52
  text "VEML7700-TR" at 101.4,29.9 h0.55
  text "QUICK CONFIGURE • SENSOR BOARD" at 76.4,27.4 h0.65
